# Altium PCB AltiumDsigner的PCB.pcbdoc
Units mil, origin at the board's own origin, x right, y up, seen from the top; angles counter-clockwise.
Board outline 2878.94 x 2328.13 mil, 2 copper layers (Top Layer, Bottom Layer); 9 components, 12 nets, 31 pads, 0 vias.
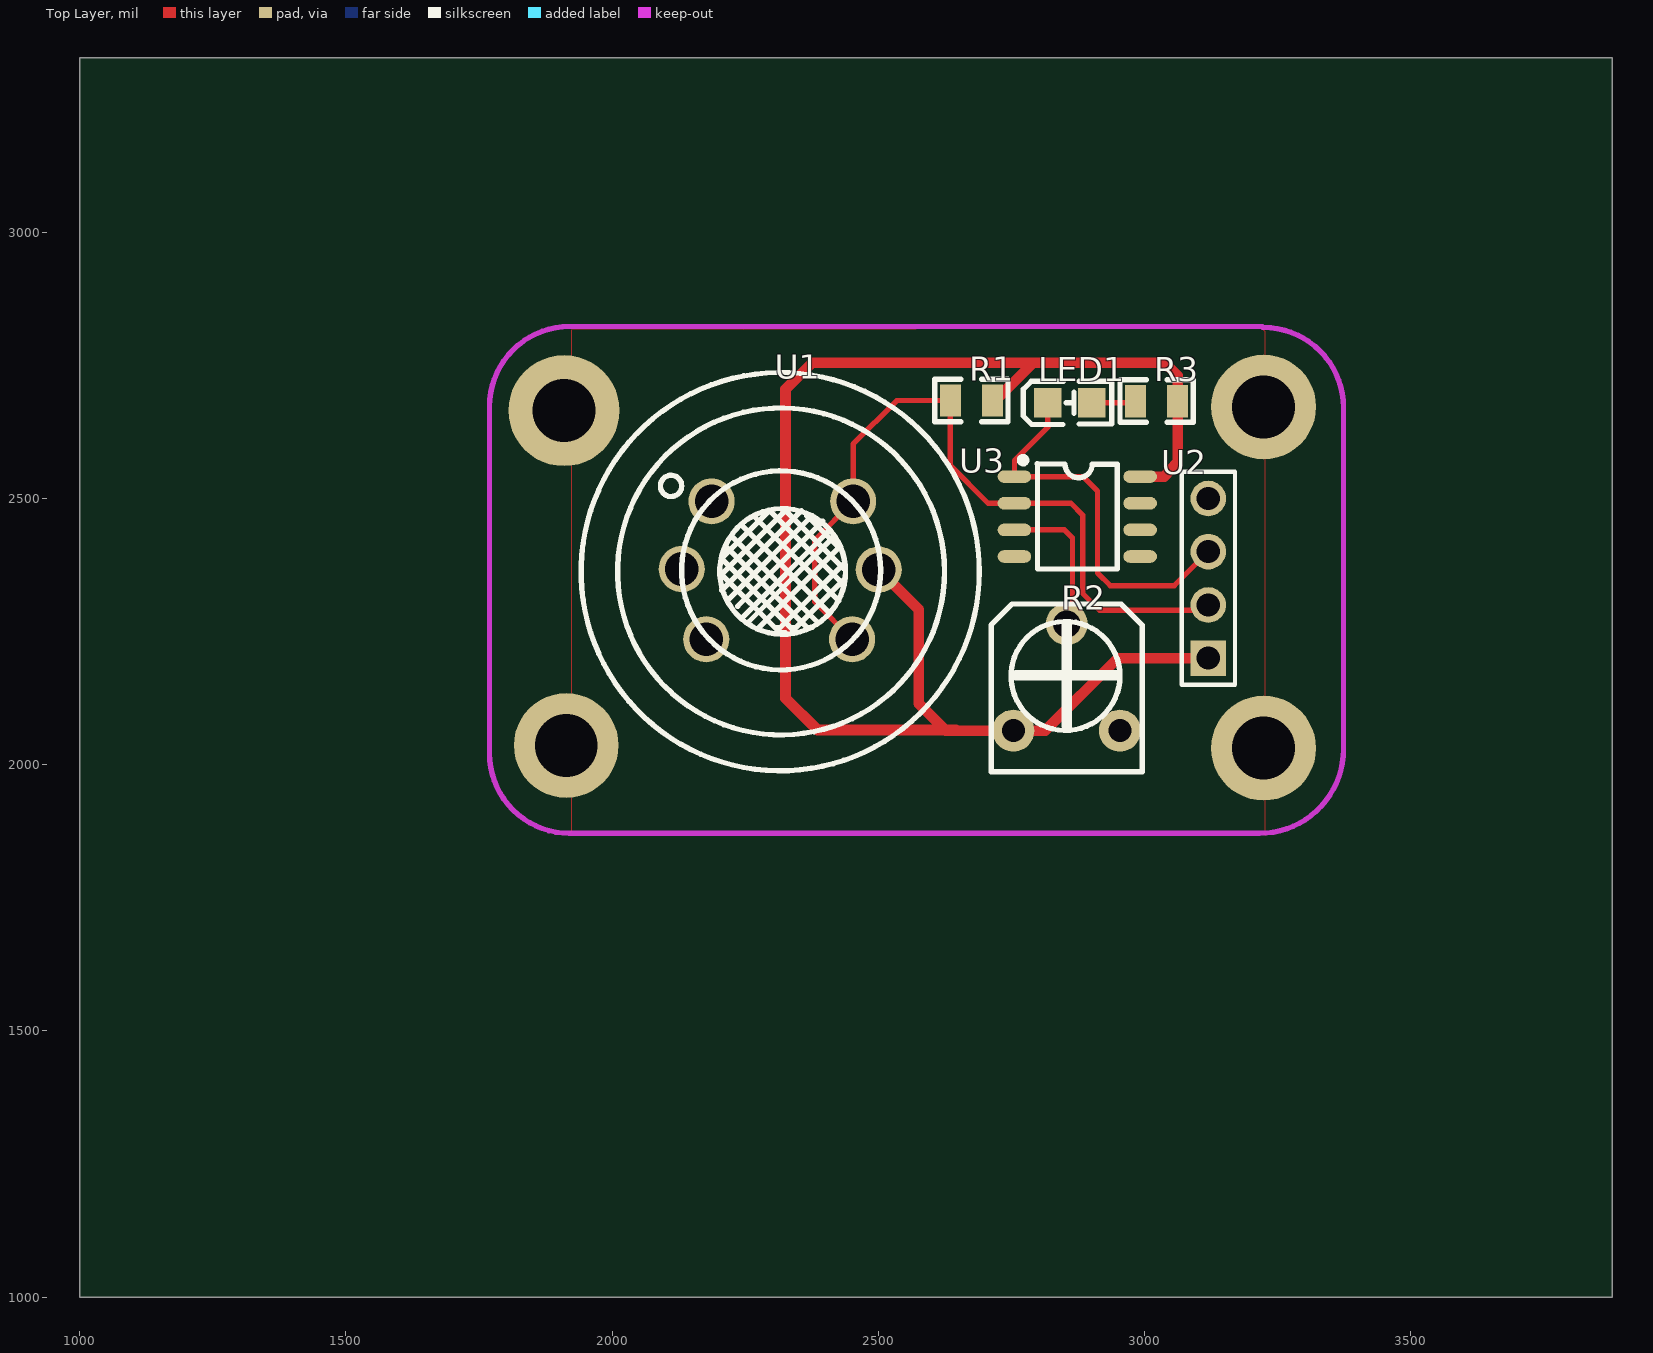
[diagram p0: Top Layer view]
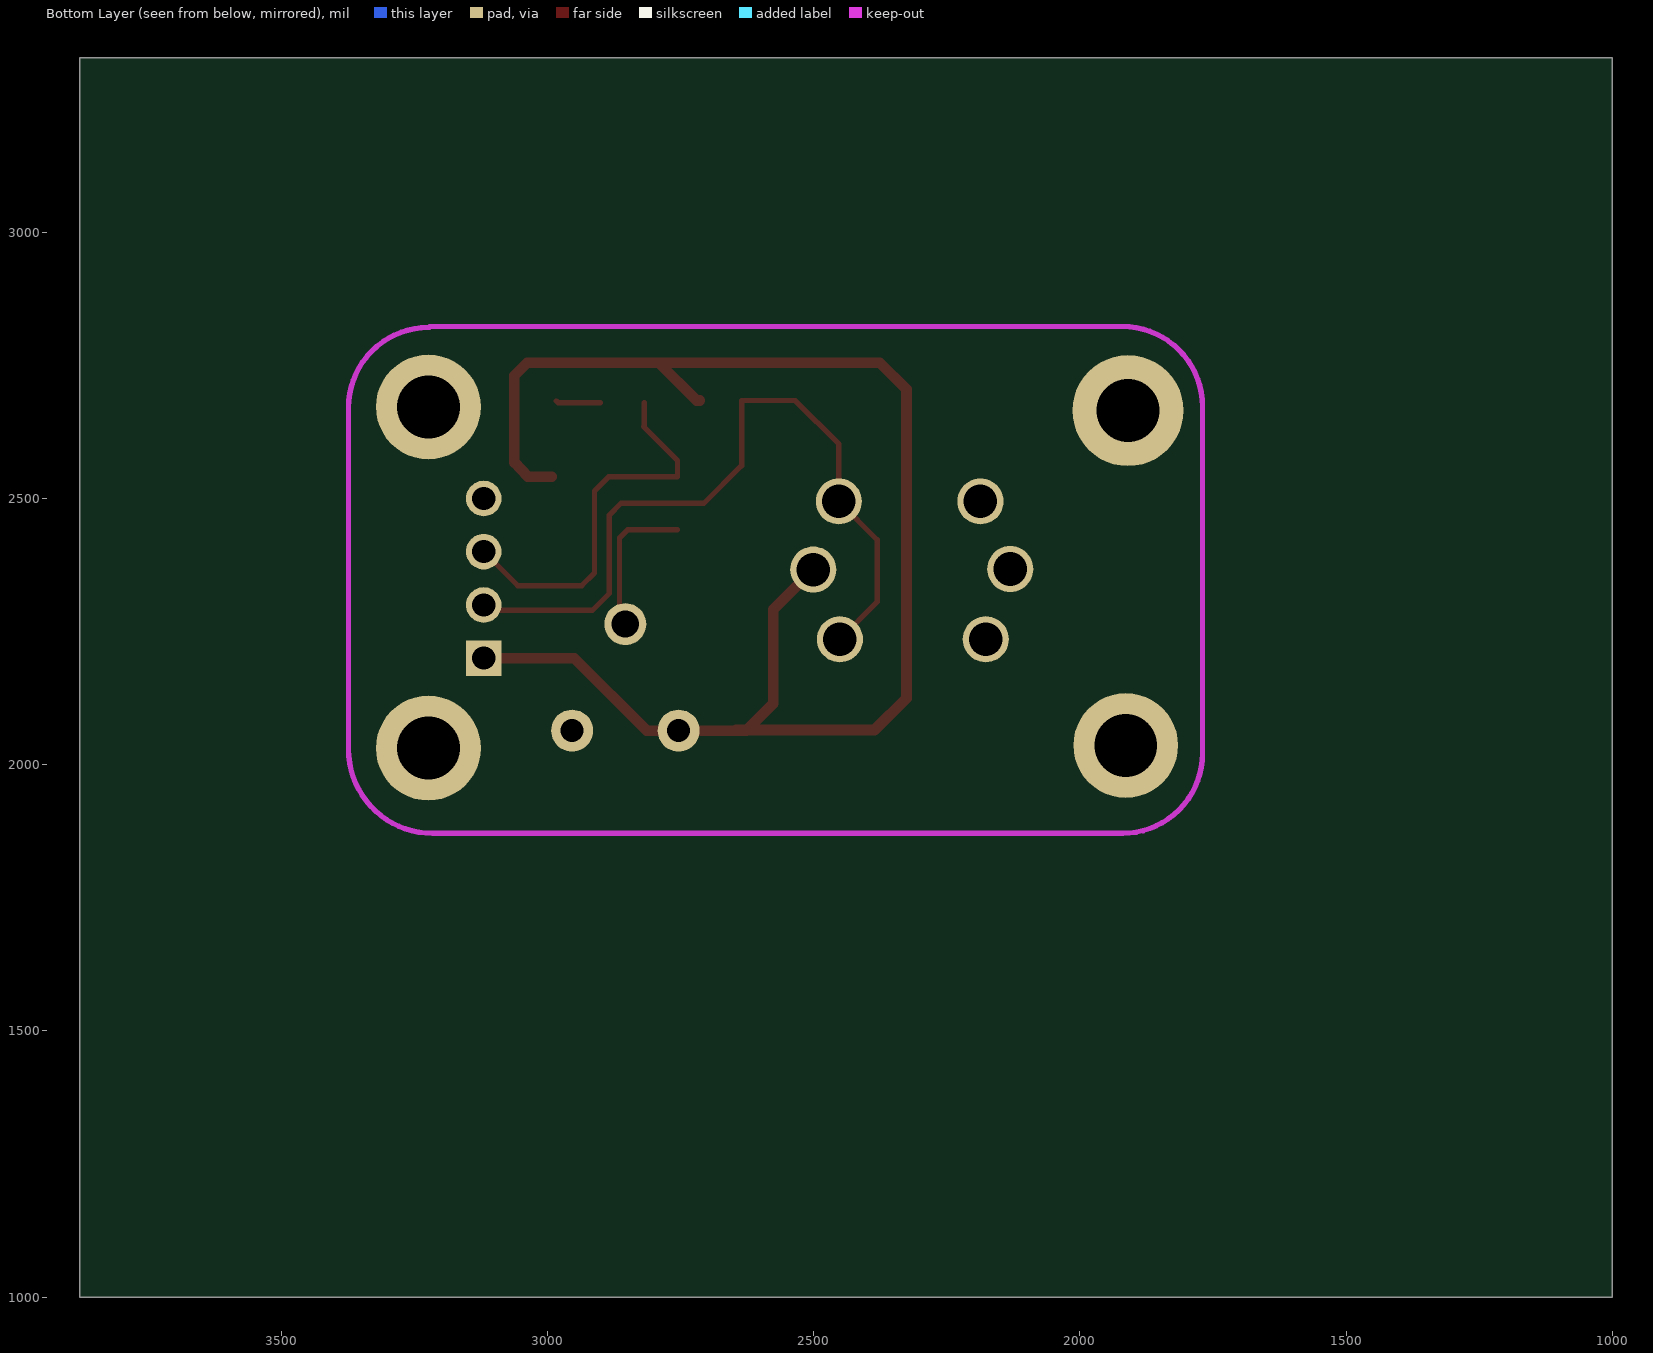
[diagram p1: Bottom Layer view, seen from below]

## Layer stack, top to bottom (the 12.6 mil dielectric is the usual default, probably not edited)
Top Layer: signal copper (thickness not stored)
Dielectric: dielectric 12.6, FR-4, Dk 4.8
Bottom Layer: signal copper (thickness not stored)

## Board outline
3878.94,1000 1000,1000 1000,3328.13 3878.94,3328.13

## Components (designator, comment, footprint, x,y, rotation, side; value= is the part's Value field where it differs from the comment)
LED1 "17-21URC/TR8" LED0805-R-RD 2859.94,2680.13 r0 top
R1 "4.7K" R0805 2674.94,2684.13 r0 top
R2 "30K" RES-ADJ-TH_VZ067TL1B202 2853.94,2164.13 r0 top
R3 "200" R0805 3022.94,2683.13 r0 top
U1 "MQ-2" SENSOR-TH_MQ-2 2315.94,2365.13 r0 top
U2 "LM393" SOP-8_L4.9-W3.9-P1.27-LS6.0-BL 2873.94,2466.13 r270 top
U3 "MTP125-1104S1" HDR-TH_4P-P2.54-V 3119.94,2350.13 r90 top
? "" ? 1719.95,2347.13 r0 top
? "" ? 2571.94,1767 r0 top

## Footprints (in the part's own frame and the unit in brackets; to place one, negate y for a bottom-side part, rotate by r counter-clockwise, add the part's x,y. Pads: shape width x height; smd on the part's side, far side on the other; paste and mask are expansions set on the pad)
HDR-TH_4P-P2.54-V [mm]
  rect 1.7x1.7 hole 1.1: 1(-3.81,0)
  round 1.7 hole 1.1: 2(-1.27,0) 3(1.27,0) 4(3.81,0)
  silkscreen extent -5.08,-1.27 5.08,1.27
LED0805-R-RD [mil]
  rect 51.2x55.1 smd: 1(41.35,0) 2(-41.35,0)
  silkscreen extent -88,-41 78,40
R0805 [mm]
  rect 1x1.55 smd: 1(-1,0) 2(1,0)
  silkscreen extent -1.75,-1.02 1.75,1.02
RES-ADJ-TH_VZ067TL1B202 [mm]
  round 2 hole 1.1: 1(-2.54,-2.54) 3(2.54,-2.54)
  round 2 hole 1.3: 2(0,2.54)
  silkscreen extent -3.6,-4.5 3.6,3.5
SENSOR-TH_MQ-2 [mm]
  round 2.2 hole 1.6: 1(-3.277,3.289) 2(-4.699,0.064) 3(-3.531,-3.289) 4(3.429,-3.289) 5(4.699,0.038) 6(3.48,3.289)
  silkscreen extent -9.5,-9.56 9.5,9.44
SOP-8_L4.9-W3.9-P1.27-LS6.0-BL [mm]
  oval 0.6x1.6 smd: 1(-1.905,-3) 2(-0.635,-3) 3(0.635,-3) 4(1.905,-3) 5(1.905,3) 6(0.635,3) 7(-0.635,3) 8(-1.905,3)
  silkscreen extent -2.84,-2.74 2.5,1.9
? [mil]

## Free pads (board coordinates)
  round 208.66 hole 118.11: 2(1909.94,2665.13)
  round 196.85 hole 118.11: 2(1913.94,2036.13) 2(3223.94,2031.13) 2(3223.94,2672.13)

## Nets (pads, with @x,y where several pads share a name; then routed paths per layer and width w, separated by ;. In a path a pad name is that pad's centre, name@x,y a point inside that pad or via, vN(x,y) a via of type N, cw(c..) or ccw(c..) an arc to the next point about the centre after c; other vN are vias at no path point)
+5V: R1.2 R2.1 R3.2 U1.5 U2.8 U3.1 | length 2946.5
  Top Layer w20: U1.5 2575.94,2291.63 2575.94,2115.13 2626.94,2064.13 R2.1 2813.94,2064.13 2949.94,2200.13 U3.1 ; 2645.68,2065.13 2385.94,2065.13 2325.94,2125.13 2325.94,2705.13 2375.94,2755.13 2790.94,2755.13 ; R1.2 2719.94,2684.13 2790.94,2755.13 ; U2.8 3036.94,2541.13 3062.34,2567.73 R3.2 ; R3.2 3062.31,2730.76 3037.94,2755.13 2790.94,2755.13
GND: R2.3 U1.1 U1.2 U1.3 U2.4 U3.4
LED1_1: LED1.1 R3.1 | length 83.5
  Top Layer w10: LED1.1 2980.57,2680.13 R3.1
S$12: 
S$21: 
S$23: 
S$26: 
S$28: 
S$557: 
U1_6: R1.1 U1.4 U1.6 U2.2 U3.2 | length 1451.5
  Top Layer w10: U1.4 2380.94,2305.63 2380.94,2422.63 U1.6 2452.94,2602.13 2534.94,2684.13 R1.1 2635.57,2561.7 2706.14,2491.13 U2.2 2861.94,2491.13 2883.94,2469.13 2883.94,2322.14 2915.94,2290.13 3109.94,2290.13 U3.2
U2_1: LED1.2 U2.1 U3.3 | length 731.7
  Top Layer w10: LED1.2 2818.59,2636.28 2819.74,2635.13 2755.83,2571.22 U2.1 2884.94,2541.13 2911.94,2514.13 2911.94,2360.13 2935.94,2336.13 3055.94,2336.13 U3.3
U2_3: R2.2 U2.3 | length 281.9
  Top Layer w10: U2.3 2849.94,2441.13 2864.94,2426.13 2864.94,2275.13 R2.2
pads on no net: U2.5 U2.6 U2.7

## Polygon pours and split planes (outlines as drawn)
GND on Top Layer (solid): 1922.94,2816.13 1922.94,1875.13 1919.94,1872.13 3222.94,1872.13 3226.94,1868.13 3226.94,2813.13 3219.94,2820.13

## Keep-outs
Keep-Out Layer:
  lines w10 net S$557: 1769.94,2021.13 ccw(c1919.94,2021.13) 1919.94,1871.13 ; 1769.94,2673.13 cw(c1919.94,2673.13) 1919.94,2823.13 ; 3215.94,1871.13 ccw(c3215.94,2029.13) 3373.94,2029.13 ; 3219.94,2823.13 cw(c3219.94,2821.13) 3221.94,2821.13 ; 3223.94,2821.13 cw(c3223.94,2671.13) 3373.94,2671.13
